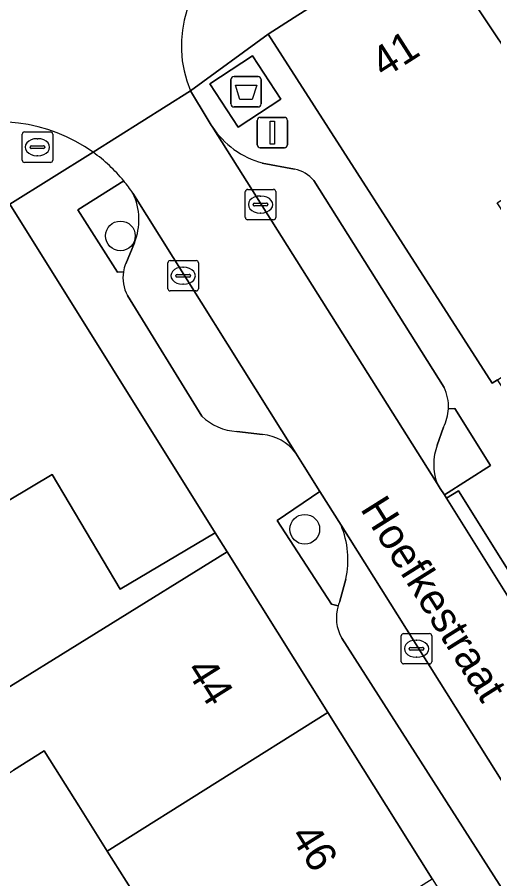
# Model space of a CAD drawing. Extents: x 161798 to 162385, y 382315 to 382833.
# Drawn here: x 162052.11 to 162067.75, y 382537.31 to 382565.6 of the extents above; entities that cross this region are included whole.
import ezdxf

# ---------------------------------------------------------------- set-up
doc = ezdxf.new("R2010")
doc.units = 0
for name, color, linetype in [('IMGEO_Afval_apart_plaats', 7, 'Continuous'), ('IMGEO_Boom', 7, 'Continuous'), ('IMGEO_Brandkraan', 7, 'Continuous'), ('IMGEO_Erf', 7, 'Continuous'), ('IMGEO_Groenvoorziening', 7, 'Continuous'), ('IMGEO_Kolk', 7, 'Continuous'), ('IMGEO_Lichtmast', 7, 'Continuous'), ('IMGEO_Openbare_ruimte_label', 7, 'Continuous'), ('IMGEO_Pand', 7, 'Continuous'), ('IMGEO_Pand_nummerreeks', 7, 'Continuous'), ('IMGEO_Parkeervlak_open', 7, 'Continuous'), ('IMGEO_Rijbaan_lokaal_open', 7, 'Continuous'), ('IMGEO_Voetpad_gesloten', 7, 'Continuous'), ('IMGEO_Voetpad_open', 7, 'Continuous')]:
    doc.layers.add(name, color=color, linetype=linetype)

msp = doc.modelspace()

# ---------------------------------------------------------------- linework, layer by layer
at = {"layer": 'IMGEO_Afval_apart_plaats'}
for p, q in [((162059.125, 382562.759), (162059.125, 382563.559)), ((162059.125, 382563.559), (162059.125, 382562.759)), ((162059.225, 382563.659), (162060.015, 382563.659)), ((162060.015, 382563.659), (162059.225, 382563.659)), ((162060.115, 382563.559), (162060.115, 382562.759)), ((162060.115, 382562.759), (162060.115, 382563.559)), ((162060.015, 382562.659), (162059.225, 382562.659)), ((162059.225, 382562.659), (162060.015, 382562.659))]:
    msp.add_line(p, q, dxfattribs=at)
msp.add_lwpolyline([(162059.268, 382563.373), (162059.972, 382563.373), (162059.823, 382562.903), (162059.417, 382562.903), (162059.268, 382563.373)], dxfattribs=at)
for centre, start, end in [((162059.225, 382563.559), 90, 180), ((162059.225, 382563.559), 90, 180), ((162060.015, 382563.559), 0, 90), ((162060.015, 382563.559), 360, 90), ((162059.225, 382562.759), 180, 270), ((162059.225, 382562.759), 180, 270), ((162060.015, 382562.759), 270, 0), ((162060.015, 382562.759), 270, 0)]:
    msp.add_arc(centre, 0.1, start, end, dxfattribs=at)
at = {"layer": 'IMGEO_Boom'}
for centre in [(162055.495, 382558.422), (162061.547, 382548.786)]:
    msp.add_circle(centre, 0.489, dxfattribs=at)
at = {"layer": 'IMGEO_Brandkraan'}
for p, q in [((162052.271, 382560.91), (162052.271, 382561.762)), ((162052.346, 382561.836), (162053.198, 382561.836)), ((162053.272, 382561.762), (162053.272, 382560.91)), ((162052.759, 382561.616), (162052.784, 382561.616)), ((162052.53, 382561.33), (162052.53, 382561.342)), ((162052.968, 382561.293), (162052.57, 382561.293)), ((162052.573, 382561.379), (162052.971, 382561.379)), ((162053.014, 382561.342), (162053.014, 382561.33)), ((162052.782, 382561.056), (162052.757, 382561.056)), ((162053.198, 382560.836), (162052.346, 382560.836))]:
    msp.add_line(p, q, dxfattribs=at)
for points in [[(162052.271, 382560.91), (162052.271, 382561.762)], [(162052.346, 382561.836), (162053.198, 382561.836)], [(162053.272, 382561.762), (162053.272, 382560.91)], [(162053.198, 382560.836), (162052.346, 382560.836)]]:
    msp.add_lwpolyline(points, dxfattribs=at)
for centre, radius, start, end in [((162052.348, 382561.76), 0.0765, 91.552, 178.448), ((162052.348, 382561.76), 0.0765, 91.552, 178.448), ((162053.196, 382561.76), 0.0765, 1.552, 88.448), ((162053.196, 382561.76), 0.0765, 1.552, 88.448), ((162052.57, 382561.339), 0.0403, 85.8775, 175.7526), ((162052.567, 382561.329), 0.0366, 178.938, 274.7102), ((162052.971, 382561.336), 0.043, 264.8664, 352.4533), ((162052.975, 382561.341), 0.0386, 1.7309, 96.639), ((162052.348, 382560.912), 0.0765, 181.552, 268.448), ((162052.348, 382560.912), 0.0765, 181.552, 268.448), ((162053.196, 382560.912), 0.0765, 271.552, 358.448), ((162053.196, 382560.912), 0.0765, 271.552, 358.448)]:
    msp.add_arc(centre, radius, start, end, dxfattribs=at)
for centre, major_axis, ratio, start_param, end_param in [((162052.758, 382561.336), (-0.387, 0.002), 0.722429, 4.712389, 7.853982), ((162052.783, 382561.336), (-0.39, 0.002), 0.717154, 1.570796, 4.712389)]:
    msp.add_ellipse(centre, major_axis=major_axis, ratio=ratio, start_param=start_param, end_param=end_param, dxfattribs=at)
at = {"layer": 'IMGEO_Erf'}
msp.add_lwpolyline([(162058.995, 382548.046), (162058.602, 382548.668), (162055.485, 382546.819), (162053.253, 382550.581), (162049.741, 382548.497), (162046.224, 382546.411), (162047.806, 382543.743), (162046.311, 382542.856), (162046.834, 382541.975), (162046.143, 382541.565), (162046.806, 382540.495)], close=True, dxfattribs=at)
msp.add_lwpolyline([(162056.097, 382536.574), (162055.064, 382538.219), (162054.134, 382539.7), (162053.365, 382540.924), (162052.997, 382541.51), (162051.981, 382540.872)], dxfattribs=at)
at = {"layer": 'IMGEO_Groenvoorziening'}
for points in [[(162055.604, 382560.23), (162054.098, 382559.274), (162055.4, 382557.229), (162055.595, 382557.244)], [(162055.668, 382557.508), (162055.958, 382558.194)], [(162065.893, 382550.294), (162065.996, 382550.131), (162066.13, 382549.916), (162067.642, 382550.881), (162066.474, 382552.754)], [(162066.474, 382552.754), (162066.263, 382552.747)], [(162066.096, 382552.139), (162065.895, 382551.554)], [(162062.739, 382548.921), (162062.044, 382550.029), (162060.646, 382549.073), (162062.425, 382546.322), (162062.643, 382546.274)], [(162062.7, 382546.427), (162062.9, 382547.152)]]:
    msp.add_lwpolyline(points, dxfattribs=at)
for centre, radius, start, end in [((162051.819, 382557.082), 4.923, 33.8571, 39.7468), ((162054.056, 382558.951), 2.047, 338.3069, 25.2751), ((162056.792, 382557.055), 1.212, 158.0556, 171.0305), ((162064.815, 382552.818), 1.45, 332.0835, 357.1991), ((162067.562, 382550.921), 1.783, 159.2194, 200.5987), ((162059.91, 382547.772), 3.054, 348.293, 22.1075), ((162063.911, 382545.889), 1.325, 156.0348, 163.0996)]:
    msp.add_arc(centre, radius, start, end, dxfattribs=at)
at = {"layer": 'IMGEO_Kolk'}
for p, q in [((162059.596, 382559.026), (162059.596, 382559.878)), ((162059.671, 382559.952), (162060.523, 382559.952)), ((162060.597, 382559.878), (162060.597, 382559.026)), ((162059.855, 382559.446), (162059.855, 382559.458)), ((162059.898, 382559.495), (162060.296, 382559.495)), ((162060.084, 382559.732), (162060.109, 382559.732)), ((162060.339, 382559.458), (162060.339, 382559.446)), ((162060.293, 382559.409), (162059.895, 382559.409)), ((162060.107, 382559.172), (162060.082, 382559.172)), ((162060.523, 382558.952), (162059.671, 382558.952)), ((162057.054, 382556.689), (162057.054, 382557.541)), ((162057.129, 382557.615), (162057.981, 382557.615)), ((162058.055, 382557.541), (162058.055, 382556.689)), ((162057.542, 382557.395), (162057.567, 382557.395)), ((162057.313, 382557.109), (162057.313, 382557.121)), ((162057.751, 382557.072), (162057.353, 382557.072)), ((162057.356, 382557.158), (162057.754, 382557.158)), ((162057.797, 382557.121), (162057.797, 382557.109)), ((162057.565, 382556.835), (162057.54, 382556.835)), ((162057.981, 382556.615), (162057.129, 382556.615)), ((162064.791, 382545.364), (162065.643, 382545.364)), ((162064.716, 382544.438), (162064.716, 382545.29)), ((162065.204, 382545.144), (162065.229, 382545.144)), ((162065.717, 382545.29), (162065.717, 382544.438)), ((162064.975, 382544.858), (162064.975, 382544.87)), ((162065.413, 382544.821), (162065.015, 382544.821)), ((162065.018, 382544.907), (162065.416, 382544.907)), ((162065.459, 382544.87), (162065.459, 382544.858)), ((162065.227, 382544.584), (162065.202, 382544.584)), ((162065.643, 382544.364), (162064.791, 382544.364))]:
    msp.add_line(p, q, dxfattribs=at)
for points in [[(162059.596, 382559.026), (162059.596, 382559.878)], [(162059.671, 382559.952), (162060.523, 382559.952)], [(162060.597, 382559.878), (162060.597, 382559.026)], [(162060.523, 382558.952), (162059.671, 382558.952)], [(162057.054, 382556.689), (162057.054, 382557.541)], [(162057.129, 382557.615), (162057.981, 382557.615)], [(162058.055, 382557.541), (162058.055, 382556.689)], [(162057.981, 382556.615), (162057.129, 382556.615)], [(162064.791, 382545.364), (162065.643, 382545.364)], [(162064.716, 382544.438), (162064.716, 382545.29)], [(162065.717, 382545.29), (162065.717, 382544.438)], [(162065.643, 382544.364), (162064.791, 382544.364)]]:
    msp.add_lwpolyline(points, dxfattribs=at)
for centre, radius, start, end in [((162059.673, 382559.876), 0.0765, 91.552, 178.448), ((162059.673, 382559.876), 0.0765, 91.552, 178.448), ((162060.521, 382559.876), 0.0765, 1.552, 88.448), ((162060.521, 382559.876), 0.0765, 1.552, 88.448), ((162059.895, 382559.455), 0.0403, 85.8775, 175.7526), ((162060.3, 382559.457), 0.0386, 1.7309, 96.639), ((162059.892, 382559.445), 0.0366, 178.938, 274.7102), ((162060.296, 382559.452), 0.043, 264.8664, 352.4533), ((162059.673, 382559.028), 0.0765, 181.552, 268.448), ((162059.673, 382559.028), 0.0765, 181.552, 268.448), ((162060.521, 382559.028), 0.0765, 271.552, 358.448), ((162060.521, 382559.028), 0.0765, 271.552, 358.448), ((162057.131, 382557.539), 0.0765, 91.552, 178.448), ((162057.131, 382557.539), 0.0765, 91.552, 178.448), ((162057.979, 382557.539), 0.0765, 1.552, 88.448), ((162057.979, 382557.539), 0.0765, 1.552, 88.448), ((162057.353, 382557.118), 0.0403, 85.8775, 175.7526), ((162057.35, 382557.108), 0.0366, 178.938, 274.7102), ((162057.754, 382557.115), 0.043, 264.8664, 352.4533), ((162057.758, 382557.12), 0.0386, 1.7309, 96.639), ((162057.131, 382556.691), 0.0765, 181.552, 268.448), ((162057.131, 382556.691), 0.0765, 181.552, 268.448), ((162057.979, 382556.691), 0.0765, 271.552, 358.448), ((162057.979, 382556.691), 0.0765, 271.552, 358.448), ((162064.793, 382545.288), 0.0765, 91.552, 178.448), ((162064.793, 382545.288), 0.0765, 91.552, 178.448), ((162065.641, 382545.288), 0.0765, 1.552, 88.448), ((162065.641, 382545.288), 0.0765, 1.552, 88.448), ((162065.015, 382544.867), 0.0403, 85.8775, 175.7526), ((162065.012, 382544.857), 0.0366, 178.938, 274.7102), ((162065.416, 382544.864), 0.043, 264.8664, 352.4533), ((162065.42, 382544.869), 0.0386, 1.7309, 96.639), ((162064.793, 382544.44), 0.0765, 181.552, 268.448), ((162064.793, 382544.44), 0.0765, 181.552, 268.448), ((162065.641, 382544.44), 0.0765, 271.552, 358.448), ((162065.641, 382544.44), 0.0765, 271.552, 358.448)]:
    msp.add_arc(centre, radius, start, end, dxfattribs=at)
for centre, major_axis, ratio, start_param, end_param in [((162060.083, 382559.452), (-0.387, 0.002), 0.722429, 4.712389, 7.853982), ((162060.108, 382559.452), (-0.39, 0.002), 0.717154, 1.570796, 4.712389), ((162057.541, 382557.115), (-0.387, 0.002), 0.722429, 4.712389, 7.853982), ((162057.566, 382557.115), (-0.39, 0.002), 0.717154, 1.570796, 4.712389), ((162065.203, 382544.864), (-0.387, 0.002), 0.722429, 4.712389, 7.853982), ((162065.228, 382544.864), (-0.39, 0.002), 0.717154, 1.570796, 4.712389)]:
    msp.add_ellipse(centre, major_axis=major_axis, ratio=ratio, start_param=start_param, end_param=end_param, dxfattribs=at)
at = {"layer": 'IMGEO_Lichtmast'}
for p, q in [((162060.087, 382562.316), (162060.877, 382562.316)), ((162060.877, 382562.316), (162060.087, 382562.316)), ((162059.987, 382561.416), (162059.987, 382562.216)), ((162059.987, 382562.216), (162059.987, 382561.416)), ((162060.977, 382562.216), (162060.977, 382561.416)), ((162060.977, 382561.416), (162060.977, 382562.216)), ((162060.877, 382561.316), (162060.087, 382561.316)), ((162060.087, 382561.316), (162060.877, 382561.316))]:
    msp.add_line(p, q, dxfattribs=at)
msp.add_lwpolyline([(162060.407, 382562.191), (162060.557, 382562.191), (162060.557, 382561.441), (162060.407, 382561.441), (162060.407, 382562.191)], dxfattribs=at)
for centre, start, end in [((162060.087, 382562.216), 90, 180), ((162060.087, 382562.216), 90, 180), ((162060.877, 382562.216), 0, 90), ((162060.877, 382562.216), 360, 90), ((162060.087, 382561.416), 180, 270), ((162060.087, 382561.416), 180, 270), ((162060.877, 382561.416), 270, 0), ((162060.877, 382561.416), 270, 0)]:
    msp.add_arc(centre, 0.1, start, end, dxfattribs=at)
at = {"layer": 'IMGEO_Pand'}
for points in [[(162071.745, 382570.4), (162070.867, 382571.77), (162068.686, 382570.371), (162068.617, 382570.478), (162065.531, 382568.448), (162070.341, 382561.247), (162070.408, 382561.144), (162073.107, 382562.874), (162075.575, 382559.025), (162078.029, 382560.599), (162077.668, 382561.162), (162073.566, 382567.561)], [(162070.408, 382561.144), (162070.341, 382561.247), (162065.531, 382568.448), (162062.645, 382566.55), (162062.571, 382566.665), (162062.299, 382566.491), (162062.308, 382566.308), (162061.202, 382565.599), (162060.346, 382565.051), (162067.224, 382554.323), (162067.7, 382553.581), (162067.877, 382553.694), (162070.553, 382555.41), (162067.86, 382559.511)], [(162045.686, 382555.874), (162049.741, 382548.497), (162053.253, 382550.581), (162055.485, 382546.819), (162058.602, 382548.668), (162051.863, 382559.469)], [(162062.305, 382542.767), (162058.995, 382548.046), (162046.806, 382540.495), (162046.563, 382540.344), (162047.758, 382538.441), (162048.467, 382537.312), (162048.608, 382537.401), (162051.048, 382538.934), (162050.439, 382539.903), (162050.638, 382540.028), (162051.626, 382540.649), (162051.981, 382540.872), (162052.997, 382541.51), (162053.365, 382540.924), (162054.134, 382539.7), (162055.064, 382538.219)], [(162065.729, 382537.304), (162062.305, 382542.767), (162055.064, 382538.219), (162056.097, 382536.574), (162056.815, 382535.43), (162056.581, 382534.402), (162056.201, 382534.163), (162055.693, 382533.844), (162054.452, 382533.065), (162055.598, 382530.942), (162058.524, 382532.779)]]:
    msp.add_lwpolyline(points, close=True, dxfattribs=at)
at = {"layer": 'IMGEO_Parkeervlak_open'}
for points in [[(162058.51, 382562.012), (162065.893, 382550.294)], [(162061.213, 382560.612), (162060.154, 382560.817)], [(162066.121, 382553.445), (162061.843, 382560.243)], [(162061.253, 382551.291), (162055.907, 382559.825)], [(162055.958, 382558.194), (162055.668, 382557.508)], [(162055.723, 382556.467), (162058.169, 382552.504)], [(162065.895, 382551.554), (162066.096, 382552.139)], [(162059.319, 382551.999), (162060.163, 382551.9)], [(162076.622, 382526.804), (162062.739, 382548.921)], [(162062.9, 382547.152), (162062.7, 382546.427)], [(162062.767, 382545.209), (162070.163, 382533.636), (162073.919, 382527.687)]]:
    msp.add_lwpolyline(points, dxfattribs=at)
for centre, radius, start, end in [((162060.924, 382563.605), 2.892, 213.4143, 254.56), ((162061.03, 382559.577), 1.051, 39.3187, 79.9651), ((162054.056, 382558.951), 2.047, 338.3069, 25.2751), ((162056.792, 382557.055), 1.212, 158.0556, 171.0305), ((162056.821, 382557.047), 1.241, 170.864, 207.8453), ((162064.821, 382552.817), 1.444, 357.218, 25.7804), ((162064.815, 382552.818), 1.45, 332.0835, 357.1991), ((162059.412, 382553.774), 1.777, 225.5984, 266.9861), ((162060.027, 382550.377), 1.53, 36.7177, 84.8968), ((162067.562, 382550.921), 1.783, 159.2194, 200.5987), ((162059.91, 382547.772), 3.054, 348.293, 22.1075), ((162063.914, 382545.882), 1.33, 162.8773, 210.405), ((162063.911, 382545.889), 1.325, 156.0348, 163.0996)]:
    msp.add_arc(centre, radius, start, end, dxfattribs=at)
at = {"layer": 'IMGEO_Rijbaan_lokaal_open'}
for points in [[(162054.599, 382561.171), (162057.798, 382563.184)], [(162066.2, 382549.805), (162066.13, 382549.916), (162065.996, 382550.131), (162065.893, 382550.294), (162058.51, 382562.012), (162058.477, 382562.063), (162058.445, 382562.115), (162058.339, 382562.28), (162057.798, 382563.184), (162054.599, 382561.171)], [(162055.907, 382559.825), (162061.253, 382551.291), (162061.473, 382550.939), (162062.044, 382550.029), (162062.739, 382548.921), (162076.622, 382526.804), (162079.529, 382528.674), (162070.806, 382542.435), (162069.1, 382545.165), (162066.2, 382549.805)]]:
    msp.add_lwpolyline(points, dxfattribs=at)
for centre, radius, start, end in [((162061.309, 382564.673), 3.814, 121.9143, 202.9777), ((162051.504, 382556.857), 5.309, 54.347, 111.7264), ((162051.531, 382556.887), 5.269, 39.3768, 54.3906), ((162051.819, 382557.082), 4.923, 33.8571, 39.7468)]:
    msp.add_arc(centre, radius, start, end, dxfattribs=at)
at = {"layer": 'IMGEO_Voetpad_gesloten'}
msp.add_lwpolyline([(162059.83, 382564.333), (162058.432, 382563.417), (162059.364, 382561.995), (162060.762, 382562.911)], close=True, dxfattribs=at)
at = {"layer": 'IMGEO_Voetpad_open'}
for points in [[(162057.798, 382563.184), (162060.346, 382565.051), (162061.202, 382565.599), (162062.308, 382566.308)], [(162100.624, 382512.613), (162097.64, 382517.372), (162094.758, 382521.967), (162091.965, 382526.421), (162089.081, 382531.02), (162086.288, 382535.473), (162083.278, 382540.272), (162080.568, 382544.594), (162078.994, 382547.104), (162078.097, 382546.514), (162078.51, 382545.898), (162074.54, 382543.391), (162072.092, 382547.296), (162070.298, 382550.02), (162067.877, 382553.694), (162067.7, 382553.581), (162067.224, 382554.323), (162060.346, 382565.051), (162057.798, 382563.184), (162058.339, 382562.28), (162058.445, 382562.115), (162058.477, 382562.063), (162058.51, 382562.012)], [(162030.29, 382551.273), (162031.842, 382548.421), (162034.161, 382549.86), (162038.271, 382552.078), (162039.174, 382552.568), (162039.345, 382552.281), (162039.715, 382552.399), (162045.686, 382555.874), (162051.863, 382559.469), (162054.599, 382561.171)], [(162054.599, 382561.171), (162051.863, 382559.469), (162058.602, 382548.668), (162058.995, 382548.046), (162062.305, 382542.767), (162065.729, 382537.304), (162069.305, 382531.6), (162072.69, 382526.201), (162073.232, 382525.358), (162076.885, 382519.522), (162079.956, 382521.492), (162078.203, 382524.285), (162076.622, 382526.804)], [(162060.154, 382560.817), (162061.213, 382560.612)], [(162055.595, 382557.244), (162055.4, 382557.229), (162054.098, 382559.274), (162055.604, 382560.23)], [(162061.843, 382560.243), (162066.121, 382553.445)], [(162058.169, 382552.504), (162055.723, 382556.467)], [(162066.263, 382552.747), (162066.474, 382552.754), (162067.642, 382550.881), (162066.13, 382549.916), (162066.2, 382549.805), (162066.597, 382550.051), (162069.427, 382545.515), (162070.549, 382546.192), (162073.822, 382541.04), (162078.659, 382541.261), (162078.76, 382538.898), (162080.123, 382538.95), (162080.223, 382536.552), (162081.579, 382536.616), (162081.697, 382534.26), (162083.059, 382534.298), (162083.105, 382531.929), (162084.466, 382532.033), (162084.647, 382529.719), (162081.003, 382529.418)], [(162060.163, 382551.9), (162059.319, 382551.999)], [(162061.473, 382550.939), (162061.253, 382551.291)], [(162062.643, 382546.274), (162062.425, 382546.322), (162060.646, 382549.073), (162062.044, 382550.029), (162061.473, 382550.939)], [(162073.919, 382527.687), (162070.163, 382533.636), (162062.767, 382545.209)]]:
    msp.add_lwpolyline(points, dxfattribs=at)
for points in [[(162059.364, 382561.995), (162058.432, 382563.417), (162059.83, 382564.333), (162060.762, 382562.911)], [(162066.597, 382550.051), (162066.2, 382549.805), (162069.1, 382545.165), (162069.493, 382545.409), (162069.427, 382545.515)]]:
    msp.add_lwpolyline(points, close=True, dxfattribs=at)
for centre, radius, start, end in [((162061.309, 382564.673), 3.814, 121.9143, 202.9777), ((162051.504, 382556.857), 5.309, 54.347, 111.7264), ((162060.924, 382563.605), 2.892, 213.4143, 254.56), ((162051.531, 382556.887), 5.269, 39.3768, 54.3906), ((162061.03, 382559.577), 1.051, 39.3187, 79.9651), ((162056.821, 382557.047), 1.241, 170.864, 207.8453), ((162064.821, 382552.817), 1.444, 357.218, 25.7804), ((162059.412, 382553.774), 1.777, 225.5984, 266.9861), ((162060.027, 382550.377), 1.53, 36.7177, 84.8968), ((162063.914, 382545.882), 1.33, 162.8773, 210.405)]:
    msp.add_arc(centre, radius, start, end, dxfattribs=at)

# ---------------------------------------------------------------- texts
at = {"layer": 'IMGEO_Openbare_ruimte_label'}
msp.add_text('Hoefkestraat', height=1, rotation=302.1329, dxfattribs=at).set_placement((162063.35, 382549.459))
at = {"layer": 'IMGEO_Pand_nummerreeks'}
for s, rotation, p in [('41', 32.5634, (162064.14, 382563.583)), ('44', 302.1313, (162057.623, 382544.166)), ('46', 302.1313, (162061.046, 382538.716))]:
    msp.add_text(s, height=1, rotation=rotation, dxfattribs=at).set_placement(p)

doc.saveas('drawing.dxf')
